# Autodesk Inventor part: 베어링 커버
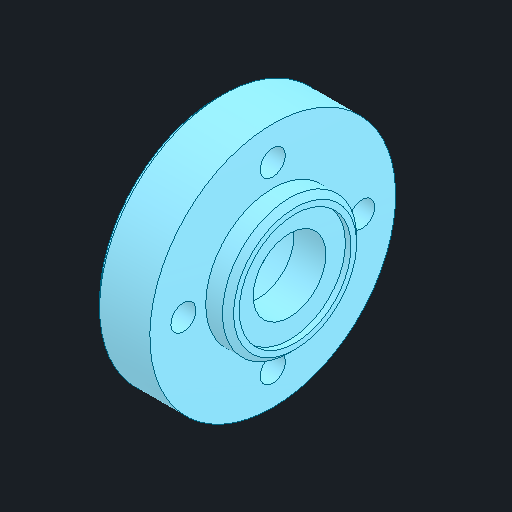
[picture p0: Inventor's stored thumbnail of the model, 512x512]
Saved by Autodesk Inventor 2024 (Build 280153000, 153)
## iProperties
Created: 2024-05
Part Number: 베어링 커버
Material: 강철, 연강
Document SubType Name: Modeling
Designer: kh_501
Density: 7.85 g/cm^3
Appearance: 기본값
Sending System: Autodesk Inventor 2025
Preprocessor: ST-DEVELOPER v20
Author: jhkim
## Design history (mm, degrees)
feature "솔리드1"
node "솔리드2"
